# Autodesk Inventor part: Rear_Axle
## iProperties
Shininess: 64.0
Length Units: 11269
Angle Units: 11279
Time Units: 11290
Mass Units: 11283
Length Display Precision: 3
Angle Display Precision: 2
Compacted: True
Part Number: Rear_Axle
Document SubType Name: Modeling
Created: 2004-03
Designer: rak
Manufacturer: Standard
Standards Organization: Custom
Description: Rear Axle
Density: 0.0
Volumn: 0.0
Area: 0.0
PropertySet Name: Model Information
Control State: 0
Master: False
Checked Out: False
Author: rak
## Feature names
1. Extrusion1
2. Chamfer1
3. Extrusion2
4. Fillet1
5. Extrusion3
6. Fillet2
